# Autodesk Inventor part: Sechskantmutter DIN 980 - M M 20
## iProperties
Shininess: 64.0
Length Units: 11269
Angle Units: 11279
Time Units: 11290
Mass Units: 11283
Length Display Precision: 3
Angle Display Precision: 2
Compacted: True
Part Number: Sechskantmutter DIN 980 - M M 20
Document SubType Name: Standard Catalog Part
Created: 2004-12
Material: Standard
Description: Sechskantmutter, mit Klemmteil, Ganzmetallmutter
Vendor: NORM8
Designer: L.Vaida
Manufacturer: Standard
Standards Organization: Custom
Density: 0.0
Volumn: 0.0
Area: 0.0
PropertySet Name: Model Information
Control State: 0
Master: False
Checked Out: False
CNS_NB: Sechskantmutter DIN 980 - M M 20
CNS_NN: DIN 980
CNS_NT: Sechskantmutter, mit Klemmteil, Ganzmetallmutter
CNS_NBSYN: Sechskantmutter DIN 980 - M $NENN.
CNS_LINA: Sechskantmutter DIN 980 - M M 20
CNS_NENN: M 20
CNS_D: 20.000
CNS_D1: 17.294
CNS_P: 2.500
CNS_M: 20.000
CNS_S: 30.000
CNS_KT: X
PSOL_IDENT_0: {E:\CAD-Programme\cadenas\partsolutions\data\23d-libs\norm\din_en_iso\muttern\muttern_mit_klemmteil\
PSOL_IDENT_1: din_980.prj},167 {M=Nenngewinde},{VTYP=3D},{NB=Sechskantmutter DIN 980 - M M 20},{NN=DIN 980},{DATE=
PSOL_IDENT_2: 29.1.2004},{GEOMDATE=26.11.2003},{VERSION=v1},{LINEID=120},{LINESUBID=-1},{WBVAR=}  {NB=Sechskantmut
PSOL_IDENT_3: ter DIN 980 - M M 20},{LINA=Sechskantmutter DIN 980 - M M 20},{KT=X},{IDNR=},{NENN=M 20},{D=20.000},
PSOL_IDENT_4: {D1=17.294},{P=2.500},{M=20.000},{S=30.000}
Title: Sechskantmutter DIN 980 - M M 20
Author: L.Vaida
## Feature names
1. Drehung1 [Revolution]
2. Extrusion1
